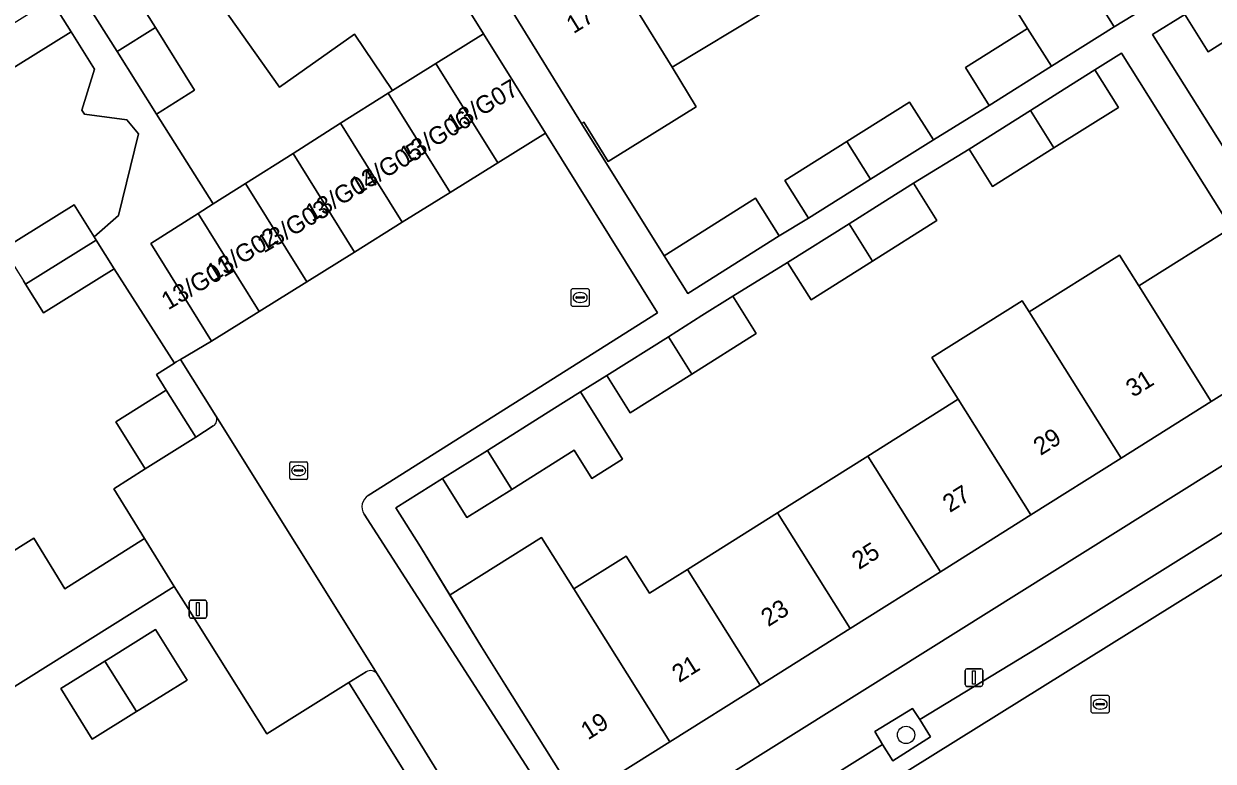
# Model space of a CAD drawing. Extents: x 159664 to 160323, y 385312 to 386115.
# Drawn here: x 160042.7 to 160109.8, y 385865.8 to 385907.3 of the extents above; entities that cross this region are included whole.
import ezdxf

# ---------------------------------------------------------------- set-up
doc = ezdxf.new("R2010")
doc.units = 0
for name, color, linetype in [('IMGEO_Boom', 7, 'Continuous'), ('IMGEO_Erf', 7, 'Continuous'), ('IMGEO_Groenvoorziening', 7, 'Continuous'), ('IMGEO_Hek', 7, 'Continuous'), ('IMGEO_Kolk', 7, 'Continuous'), ('IMGEO_Lichtmast', 7, 'Continuous'), ('IMGEO_Muur', 7, 'Continuous'), ('IMGEO_Pand', 7, 'Continuous'), ('IMGEO_Pand_nummerreeks', 7, 'Continuous'), ('IMGEO_Parkeervlak_open', 7, 'Continuous'), ('IMGEO_Rijbaan_lokaal_open', 7, 'Continuous'), ('IMGEO_Rioolput', 7, 'Continuous'), ('IMGEO_Voetpad_open', 7, 'Continuous')]:
    doc.layers.add(name, color=color, linetype=linetype)

msp = doc.modelspace()

# ---------------------------------------------------------------- linework, layer by layer
at = {"layer": 'IMGEO_Boom'}
msp.add_circle((160092.484, 385867.255), 0.489, dxfattribs=at)
at = {"layer": 'IMGEO_Erf'}
for points in [[(160126.839, 385908.47), (160123.221, 385914.292), (160119.716, 385912.09), (160118.382, 385914.213), (160115.296, 385912.328), (160116.62, 385910.22), (160112.979, 385907.932), (160109.521, 385905.76), (160108.197, 385907.868), (160106.387, 385906.731), (160112.564, 385896.901), (160117.776, 385900.176), (160122.877, 385903.38), (160121.717, 385905.252)], [(160093.943, 385888.53), (160099.032, 385891.727), (160099.43, 385891.094), (160104.519, 385894.291), (160105.604, 385892.565), (160110.817, 385895.84), (160104.64, 385905.681), (160103.136, 385904.736), (160104.46, 385902.628), (160100.815, 385900.338), (160097.361, 385898.168), (160096.037, 385900.276), (160092.906, 385898.349), (160094.23, 385896.241), (160090.592, 385893.956), (160087.131, 385891.781), (160085.807, 385893.889), (160082.713, 385891.979), (160084.037, 385889.871), (160080.399, 385887.585), (160076.938, 385885.411), (160075.614, 385887.519), (160074.124, 385886.584), (160076.502, 385882.799), (160074.763, 385881.707), (160073.764, 385883.296), (160070.256, 385881.092), (160067.724, 385879.501), (160066.344, 385881.698), (160063.721, 385880.05), (160065.101, 385877.853), (160066.757, 385875.136), (160066.776, 385875.148), (160071.939, 385878.386), (160073.757, 385875.486), (160076.705, 385877.338), (160078.024, 385875.238), (160079.31, 385876.045), (160080.158, 385876.578), (160085.247, 385879.775), (160090.337, 385882.973), (160095.426, 385886.17)], [(160017.562, 385899.151), (160016.976, 385898.786), (160016.864, 385898.967), (160013.411, 385904.508), (160011.524, 385903.327), (160035.946, 385864.298), (160048.683, 385843.877), (160069.417, 385856.837), (160067.895, 385859.287), (160061.072, 385870.217), (160056.435, 385867.318), (160052.008, 385874.381), (160051.226, 385875.622), (160036.993, 385866.722), (160033.548, 385872.248), (160030.317, 385877.411), (160029.732, 385877.045), (160029.621, 385877.223), (160026.283, 385882.566), (160026.158, 385882.766), (160027.345, 385883.508), (160024.13, 385888.65), (160020.789, 385893.991)], [(160116.716, 385886.45), (160114.912, 385889.321), (160109.699, 385886.046), (160104.61, 385882.849), (160099.521, 385879.652), (160094.432, 385876.454), (160089.342, 385873.256), (160084.253, 385870.059), (160079.165, 385866.862), (160074.076, 385863.665), (160075.884, 385860.864)], [(160050.171, 385873.193), (160051.948, 385870.346), (160049.274, 385868.684), (160049.094, 385868.572), (160046.6, 385867.021), (160044.828, 385869.865), (160047.316, 385871.414), (160047.5, 385871.529)]]:
    msp.add_lwpolyline(points, close=True, dxfattribs=at)
for points in [[(160101.284, 385911.84), (160104.221, 385907.166), (160107.37, 385909.108)], [(160047.941, 385910.651), (160050.158, 385907.127), (160052.374, 385903.603), (160050.216, 385902.245), (160053.421, 385897.182), (160055.247, 385898.338), (160057.926, 385900.034), (160060.605, 385901.73), (160063.284, 385903.426), (160063.535, 385903.585), (160061.393, 385906.756), (160057.162, 385903.768), (160053.366, 385909.143)], [(160084.541, 385908.057), (160079.289, 385904.884), (160080.657, 385902.663), (160075.692, 385899.577), (160074.315, 385901.792), (160074.183, 385901.71), (160078.841, 385894.266), (160083.99, 385897.501), (160085.324, 385895.378), (160086.982, 385896.372), (160085.644, 385898.503), (160089.148, 385900.705), (160092.688, 385902.929), (160094.027, 385900.798), (160097.176, 385902.74), (160095.838, 385904.871), (160099.342, 385907.073), (160097.759, 385909.621)], [(160041.596, 385894.65), (160045.576, 385897.131), (160046.701, 385895.328), (160048.08, 385896.529), (160049.216, 385901.132), (160048.554, 385901.921), (160046.156, 385902.244), (160046.014, 385902.47), (160046.729, 385904.777), (160045.416, 385906.887), (160041.433, 385904.408)], [(160041.591, 385877.278), (160043.3, 385878.347), (160045.063, 385875.496), (160049.546, 385878.331), (160047.808, 385881.122), (160049.592, 385882.259), (160047.93, 385884.908), (160050.768, 385886.689), (160050.227, 385887.569), (160051.229, 385888.21), (160047.826, 385893.524), (160043.846, 385891.042), (160042.835, 385892.664), (160042.721, 385892.846)]]:
    msp.add_lwpolyline(points, dxfattribs=at)
at = {"layer": 'IMGEO_Groenvoorziening'}
msp.add_lwpolyline([(160093.873, 385867.136), (160093.257, 385868.13), (160092.858, 385868.751), (160090.725, 385867.449), (160091.151, 385866.716), (160091.737, 385865.792)], close=True, dxfattribs=at)
at = {"layer": 'IMGEO_Hek'}
for points in [[(160051.574, 385888.418), (160053.317, 385889.442)], [(160051.328, 385888.274), (160051.574, 385888.418)], [(160052.008, 385874.381), (160051.226, 385875.622)]]:
    msp.add_lwpolyline(points, dxfattribs=at)
at = {"layer": 'IMGEO_Kolk'}
for p, q in [((160073.686, 385892.41), (160074.538, 385892.41)), ((160073.611, 385891.484), (160073.611, 385892.336)), ((160073.87, 385891.904), (160073.87, 385891.916)), ((160074.308, 385891.867), (160073.91, 385891.867)), ((160073.913, 385891.953), (160074.311, 385891.953)), ((160074.099, 385892.19), (160074.124, 385892.19)), ((160074.354, 385891.916), (160074.354, 385891.904)), ((160074.612, 385892.336), (160074.612, 385891.484)), ((160074.538, 385891.41), (160073.686, 385891.41)), ((160074.122, 385891.63), (160074.097, 385891.63)), ((160057.735, 385881.728), (160057.735, 385882.58)), ((160057.81, 385882.654), (160058.662, 385882.654)), ((160058.223, 385882.434), (160058.248, 385882.434)), ((160058.736, 385882.58), (160058.736, 385881.728)), ((160058.662, 385881.654), (160057.81, 385881.654)), ((160057.994, 385882.148), (160057.994, 385882.16)), ((160058.432, 385882.111), (160058.034, 385882.111)), ((160058.037, 385882.197), (160058.435, 385882.197)), ((160058.246, 385881.874), (160058.221, 385881.874)), ((160058.478, 385882.16), (160058.478, 385882.148))]:
    msp.add_line(p, q, dxfattribs=at)
for points in [[(160073.686, 385892.41), (160074.538, 385892.41)], [(160073.611, 385891.484), (160073.611, 385892.336)], [(160074.612, 385892.336), (160074.612, 385891.484)], [(160074.538, 385891.41), (160073.686, 385891.41)], [(160057.735, 385881.728), (160057.735, 385882.58)], [(160057.81, 385882.654), (160058.662, 385882.654)], [(160058.736, 385882.58), (160058.736, 385881.728)], [(160058.662, 385881.654), (160057.81, 385881.654)]]:
    msp.add_lwpolyline(points, dxfattribs=at)
for centre, radius, start, end in [((160073.688, 385892.334), 0.0765, 91.55205, 178.44795), ((160073.688, 385892.334), 0.0765, 91.55205, 178.44795), ((160074.536, 385892.334), 0.0765, 1.55205, 88.44795), ((160074.536, 385892.334), 0.0765, 1.55205, 88.44795), ((160073.91, 385891.913), 0.0403, 85.87752, 175.75265), ((160073.907, 385891.903), 0.0366, 178.93798, 274.71019), ((160074.311, 385891.91), 0.043, 264.86636, 352.45326), ((160074.315, 385891.915), 0.0386, 1.73085, 96.63898), ((160073.688, 385891.486), 0.0765, 181.55205, 268.44795), ((160073.688, 385891.486), 0.0765, 181.55205, 268.44795), ((160074.536, 385891.486), 0.0765, 271.55205, 358.44795), ((160074.536, 385891.486), 0.0765, 271.55205, 358.44795), ((160057.812, 385882.578), 0.0765, 91.55205, 178.44795), ((160057.812, 385882.578), 0.0765, 91.55205, 178.44795), ((160058.66, 385882.578), 0.0765, 1.55205, 88.44795), ((160058.66, 385882.578), 0.0765, 1.55205, 88.44795), ((160057.812, 385881.73), 0.0765, 181.55205, 268.44795), ((160057.812, 385881.73), 0.0765, 181.55205, 268.44795), ((160058.034, 385882.157), 0.0403, 85.87752, 175.75265), ((160058.031, 385882.147), 0.0366, 178.93798, 274.71019), ((160058.435, 385882.154), 0.043, 264.86636, 352.45326), ((160058.439, 385882.159), 0.0386, 1.73085, 96.63898), ((160058.66, 385881.73), 0.0765, 271.55205, 358.44795), ((160058.66, 385881.73), 0.0765, 271.55205, 358.44795)]:
    msp.add_arc(centre, radius, start, end, dxfattribs=at)
for centre, major_axis, ratio, start_param, end_param in [((160074.098, 385891.91), (-0.387, 0.002), 0.722429, 4.712389, 7.853982), ((160074.123, 385891.91), (-0.39, 0.002), 0.717154, 1.570796, 4.712389), ((160058.222, 385882.154), (-0.387, 0.002), 0.722429, 4.712389, 7.853982), ((160058.247, 385882.154), (-0.39, 0.002), 0.717154, 1.570796, 4.712389)]:
    msp.add_ellipse(centre, major_axis=major_axis, ratio=ratio, start_param=start_param, end_param=end_param, dxfattribs=at)
at = {"layer": 'IMGEO_Lichtmast'}
for p, q in [((160052.067, 385873.943), (160052.067, 385874.743)), ((160052.067, 385874.743), (160052.067, 385873.943)), ((160052.167, 385874.843), (160052.957, 385874.843)), ((160052.957, 385874.843), (160052.167, 385874.843)), ((160053.057, 385874.743), (160053.057, 385873.943)), ((160053.057, 385873.943), (160053.057, 385874.743)), ((160052.957, 385873.843), (160052.167, 385873.843)), ((160052.167, 385873.843), (160052.957, 385873.843)), ((160095.919, 385870.986), (160096.709, 385870.986)), ((160096.709, 385870.986), (160095.919, 385870.986)), ((160095.819, 385870.086), (160095.819, 385870.886)), ((160095.819, 385870.886), (160095.819, 385870.086)), ((160096.809, 385870.886), (160096.809, 385870.086)), ((160096.809, 385870.086), (160096.809, 385870.886)), ((160096.709, 385869.986), (160095.919, 385869.986)), ((160095.919, 385869.986), (160096.709, 385869.986))]:
    msp.add_line(p, q, dxfattribs=at)
for points in [[(160052.487, 385874.718), (160052.637, 385874.718), (160052.637, 385873.968), (160052.487, 385873.968), (160052.487, 385874.718)], [(160096.239, 385870.861), (160096.389, 385870.861), (160096.389, 385870.111), (160096.239, 385870.111), (160096.239, 385870.861)]]:
    msp.add_lwpolyline(points, dxfattribs=at)
for centre, start, end in [((160052.167, 385874.743), 90, 180), ((160052.167, 385874.743), 90, 180), ((160052.957, 385874.743), 0, 90), ((160052.957, 385874.743), 360, 90), ((160052.167, 385873.943), 180, 270), ((160052.167, 385873.943), 180, 270), ((160052.957, 385873.943), 270, 0), ((160052.957, 385873.943), 270, 0), ((160095.919, 385870.886), 90, 180), ((160095.919, 385870.886), 90, 180), ((160096.709, 385870.886), 0, 90), ((160096.709, 385870.886), 360, 90), ((160095.919, 385870.086), 180, 270), ((160095.919, 385870.086), 180, 270), ((160096.709, 385870.086), 270, 0), ((160096.709, 385870.086), 270, 0)]:
    msp.add_arc(centre, 0.1, start, end, dxfattribs=at)
at = {"layer": 'IMGEO_Muur'}
for points in [[(160074.183, 385901.71), (160078.841, 385894.266)], [(160050.768, 385886.689), (160050.227, 385887.569), (160051.328, 385888.274)], [(160049.546, 385878.331), (160047.808, 385881.122), (160049.592, 385882.259)], [(160065.101, 385877.853), (160068.541, 385872.21)], [(160052.008, 385874.381), (160056.435, 385867.318), (160061.072, 385870.217)], [(160061.072, 385870.217), (160067.895, 385859.287)]]:
    msp.add_lwpolyline(points, dxfattribs=at)
at = {"layer": 'IMGEO_Pand'}
for points in [[(160066.34, 385910.485), (160067.916, 385911.581), (160064.485, 385916.622), (160056.342, 385911.145), (160053.366, 385909.143), (160057.162, 385903.768), (160061.393, 385906.756), (160063.535, 385903.585), (160065.974, 385905.104), (160068.657, 385906.776)], [(160080.357, 385914.713), (160080.13, 385915.074), (160074.992, 385911.86), (160075.203, 385911.518), (160079.289, 385904.884), (160084.541, 385908.057)], [(160075.203, 385911.518), (160074.992, 385911.86), (160069.893, 385908.671), (160070.091, 385908.35), (160074.183, 385901.71), (160074.315, 385901.792), (160075.692, 385899.577), (160080.657, 385902.663), (160079.289, 385904.884)], [(160104.221, 385907.166), (160101.284, 385911.84), (160097.759, 385909.621), (160099.342, 385907.073), (160100.678, 385904.94)], [(160050.158, 385907.127), (160047.941, 385910.651), (160045.783, 385909.294), (160047.999, 385905.77)], [(160108.197, 385907.868), (160109.521, 385905.76), (160112.979, 385907.932), (160111.669, 385910.05)], [(160040.307, 385906.205), (160041.433, 385904.408), (160045.416, 385906.887), (160044.292, 385908.693)], [(160047.999, 385905.77), (160050.216, 385902.245), (160052.374, 385903.603), (160050.158, 385907.127)], [(160072.156, 385901.175), (160068.657, 385906.776), (160065.974, 385905.104), (160069.465, 385899.499)], [(160095.838, 385904.871), (160097.176, 385902.74), (160100.678, 385904.94), (160099.342, 385907.073)], [(160065.974, 385905.104), (160063.535, 385903.585), (160063.284, 385903.426), (160066.773, 385897.823), (160069.465, 385899.499)], [(160104.46, 385902.628), (160103.136, 385904.736), (160101.399, 385903.645), (160099.509, 385902.458), (160100.815, 385900.338)], [(160064.082, 385896.147), (160066.773, 385897.823), (160063.284, 385903.426), (160060.605, 385901.73)], [(160094.027, 385900.798), (160092.688, 385902.929), (160089.148, 385900.705), (160090.484, 385898.572)], [(160096.037, 385900.276), (160097.361, 385898.168), (160100.815, 385900.338), (160099.509, 385902.458)], [(160060.605, 385901.73), (160057.926, 385900.034), (160061.391, 385894.47), (160064.082, 385896.147)], [(160085.644, 385898.503), (160086.982, 385896.372), (160090.484, 385898.572), (160089.148, 385900.705)], [(160057.926, 385900.034), (160055.247, 385898.338), (160058.7, 385892.794), (160061.391, 385894.47)], [(160055.247, 385898.338), (160053.421, 385897.182), (160052.568, 385896.642), (160056.008, 385891.118), (160058.7, 385892.794)], [(160094.23, 385896.241), (160092.906, 385898.349), (160091.169, 385897.258), (160089.279, 385896.071), (160090.592, 385893.956)], [(160042.835, 385892.664), (160046.815, 385895.144), (160046.701, 385895.328), (160045.576, 385897.131), (160041.596, 385894.65), (160042.721, 385892.846)], [(160085.324, 385895.378), (160083.99, 385897.501), (160078.841, 385894.266), (160080.175, 385892.143)], [(160049.895, 385894.95), (160053.317, 385889.442), (160056.008, 385891.118), (160052.568, 385896.642)], [(160085.807, 385893.889), (160087.131, 385891.781), (160090.592, 385893.956), (160089.279, 385896.071)], [(160109.699, 385886.046), (160114.912, 385889.321), (160112.252, 385893.554), (160110.817, 385895.84), (160105.604, 385892.565)], [(160043.846, 385891.042), (160047.826, 385893.524), (160046.815, 385895.144), (160042.835, 385892.664)], [(160105.604, 385892.565), (160104.519, 385894.291), (160099.43, 385891.094), (160100.515, 385889.367), (160104.61, 385882.849), (160109.699, 385886.046)], [(160084.037, 385889.871), (160082.713, 385891.979), (160080.976, 385890.888), (160079.086, 385889.701), (160080.399, 385887.585)], [(160100.515, 385889.367), (160099.43, 385891.094), (160099.032, 385891.727), (160093.943, 385888.53), (160095.426, 385886.17), (160099.521, 385879.652), (160104.61, 385882.849)], [(160076.938, 385885.411), (160080.399, 385887.585), (160079.086, 385889.701), (160075.614, 385887.519)], [(160050.768, 385886.689), (160047.93, 385884.908), (160049.592, 385882.259), (160052.431, 385884.04)], [(160074.124, 385886.584), (160072.518, 385885.577), (160068.882, 385883.292), (160070.256, 385881.092), (160073.764, 385883.296), (160074.763, 385881.707), (160076.502, 385882.799)], [(160094.432, 385876.454), (160099.521, 385879.652), (160095.426, 385886.17), (160090.337, 385882.973)], [(160068.882, 385883.292), (160066.344, 385881.698), (160067.724, 385879.501), (160070.256, 385881.092)], [(160089.342, 385873.256), (160094.432, 385876.454), (160090.337, 385882.973), (160085.247, 385879.775)], [(160085.247, 385879.775), (160080.158, 385876.578), (160084.253, 385870.059), (160089.342, 385873.256)], [(160051.226, 385875.622), (160049.546, 385878.331), (160045.063, 385875.496), (160043.3, 385878.347), (160041.591, 385877.278), (160033.548, 385872.248), (160036.993, 385866.722)], [(160073.757, 385875.486), (160071.939, 385878.386), (160066.776, 385875.148), (160066.757, 385875.136), (160068.541, 385872.21), (160069.86, 385870.109), (160073.955, 385863.589), (160074.076, 385863.665), (160079.165, 385866.862)], [(160080.158, 385876.578), (160079.31, 385876.045), (160078.024, 385875.238), (160076.705, 385877.338), (160073.757, 385875.486), (160079.165, 385866.862), (160084.253, 385870.059)], [(160047.316, 385871.414), (160049.094, 385868.572), (160049.274, 385868.684), (160051.948, 385870.346), (160050.171, 385873.193), (160047.5, 385871.529)], [(160044.828, 385869.865), (160046.6, 385867.021), (160049.094, 385868.572), (160047.316, 385871.414)]]:
    msp.add_lwpolyline(points, close=True, dxfattribs=at)
at = {"layer": 'IMGEO_Parkeervlak_open'}
for points in [[(160063.145, 385846.843), (160091.556, 385864.586), (160112.548, 385877.672), (160134.283, 385891.268)], [(160122.453, 385884.847), (160121.825, 385885.847), (160101.83, 385873.354), (160099.827, 385872.1), (160093.257, 385868.13), (160093.873, 385867.136), (160091.737, 385865.792), (160091.151, 385866.716), (160082.406, 385861.229), (160083.032, 385860.228)], [(160062.663, 385870.691), (160053.567, 385885.245)], [(160053.422, 385884.668), (160052.431, 385884.04), (160049.592, 385882.259), (160047.808, 385881.122), (160049.546, 385878.331), (160051.226, 385875.622), (160052.008, 385874.381), (160056.435, 385867.318), (160061.072, 385870.217), (160062.04, 385870.818)]]:
    msp.add_lwpolyline(points, dxfattribs=at)
for centre, radius, start, end in [((160053.188, 385885.034), 0.434, 302.62155, 29.16582), ((160062.275, 385870.379), 0.498, 38.79059, 118.16539)]:
    msp.add_arc(centre, radius, start, end, dxfattribs=at)
at = {"layer": 'IMGEO_Rijbaan_lokaal_open'}
for points in [[(160062.163, 385880.749), (160078.47, 385891.036), (160072.156, 385901.175), (160069.465, 385899.499), (160066.773, 385897.823), (160064.082, 385896.147), (160061.391, 385894.47), (160058.7, 385892.794), (160056.008, 385891.118), (160053.317, 385889.442), (160051.574, 385888.418), (160053.567, 385885.245), (160062.663, 385870.691), (160070.726, 385857.635), (160074.573, 385860.069), (160061.925, 385879.702)], [(160112.548, 385877.672), (160091.556, 385864.586)]]:
    msp.add_lwpolyline(points, dxfattribs=at)
msp.add_arc((160062.567, 385880.107), 0.759, 122.15666, 212.23007, dxfattribs=at)
at = {"layer": 'IMGEO_Rioolput'}
for p, q in [((160102.931, 385868.56), (160102.931, 385869.412)), ((160103.006, 385869.486), (160103.858, 385869.486)), ((160103.19, 385868.98), (160103.19, 385868.992)), ((160103.628, 385868.943), (160103.23, 385868.943)), ((160103.233, 385869.029), (160103.631, 385869.029)), ((160103.419, 385869.266), (160103.444, 385869.266)), ((160103.674, 385868.992), (160103.674, 385868.98)), ((160103.932, 385869.412), (160103.932, 385868.56)), ((160103.858, 385868.486), (160103.006, 385868.486)), ((160103.442, 385868.706), (160103.417, 385868.706))]:
    msp.add_line(p, q, dxfattribs=at)
for points in [[(160102.931, 385868.56), (160102.931, 385869.412)], [(160103.006, 385869.486), (160103.858, 385869.486)], [(160103.932, 385869.412), (160103.932, 385868.56)], [(160103.858, 385868.486), (160103.006, 385868.486)]]:
    msp.add_lwpolyline(points, dxfattribs=at)
for centre, radius, start, end in [((160103.008, 385869.41), 0.0765, 91.55205, 178.44795), ((160103.008, 385869.41), 0.0765, 91.55205, 178.44795), ((160103.23, 385868.989), 0.0403, 85.87752, 175.75265), ((160103.227, 385868.979), 0.0366, 178.93798, 274.71019), ((160103.631, 385868.986), 0.043, 264.86636, 352.45326), ((160103.635, 385868.991), 0.0386, 1.73085, 96.63898), ((160103.856, 385869.41), 0.0765, 1.55205, 88.44795), ((160103.856, 385869.41), 0.0765, 1.55205, 88.44795), ((160103.008, 385868.562), 0.0765, 181.55205, 268.44795), ((160103.008, 385868.562), 0.0765, 181.55205, 268.44795), ((160103.856, 385868.562), 0.0765, 271.55205, 358.44795), ((160103.856, 385868.562), 0.0765, 271.55205, 358.44795)]:
    msp.add_arc(centre, radius, start, end, dxfattribs=at)
for centre, major_axis, ratio, start_param, end_param in [((160103.418, 385868.986), (-0.387, 0.002), 0.722429, 4.712389, 7.853982), ((160103.443, 385868.986), (-0.39, 0.002), 0.717154, 1.570796, 4.712389)]:
    msp.add_ellipse(centre, major_axis=major_axis, ratio=ratio, start_param=start_param, end_param=end_param, dxfattribs=at)
at = {"layer": 'IMGEO_Voetpad_open'}
for points in [[(160066.34, 385910.485), (160068.657, 385906.776), (160072.156, 385901.175), (160078.47, 385891.036), (160062.163, 385880.749)], [(160044.292, 385908.693), (160045.416, 385906.887), (160046.729, 385904.777), (160046.014, 385902.47), (160046.156, 385902.244), (160048.554, 385901.921), (160049.216, 385901.132), (160048.08, 385896.529), (160046.701, 385895.328), (160046.815, 385895.144), (160047.826, 385893.524), (160051.229, 385888.21), (160051.328, 385888.274), (160051.574, 385888.418), (160053.317, 385889.442), (160049.895, 385894.95), (160052.568, 385896.642), (160053.421, 385897.182), (160050.216, 385902.245), (160047.999, 385905.77), (160045.783, 385909.294)], [(160107.37, 385909.108), (160104.221, 385907.166), (160100.678, 385904.94), (160097.176, 385902.74), (160094.027, 385900.798), (160090.484, 385898.572), (160086.982, 385896.372), (160085.324, 385895.378), (160080.175, 385892.143), (160078.841, 385894.266), (160074.183, 385901.71), (160070.091, 385908.35)], [(160106.387, 385906.731), (160108.197, 385907.868)], [(160112.564, 385896.901), (160106.387, 385906.731)], [(160073.955, 385863.589), (160069.86, 385870.109), (160068.541, 385872.21), (160066.757, 385875.136), (160065.101, 385877.853), (160063.721, 385880.05), (160066.344, 385881.698), (160068.882, 385883.292), (160072.518, 385885.577), (160074.124, 385886.584), (160075.614, 385887.519), (160079.086, 385889.701), (160080.976, 385890.888), (160082.713, 385891.979), (160085.807, 385893.889), (160089.279, 385896.071), (160091.169, 385897.258), (160092.906, 385898.349), (160096.037, 385900.276), (160099.509, 385902.458), (160101.399, 385903.645), (160103.136, 385904.736), (160104.64, 385905.681), (160110.817, 385895.84)], [(160141.001, 385901.665), (160139.28, 385900.589), (160118.445, 385887.533), (160116.716, 385886.45), (160075.884, 385860.864), (160074.573, 385860.069), (160070.726, 385857.635), (160069.417, 385856.837), (160048.683, 385843.877), (160050.819, 385840.388)], [(160051.574, 385888.418), (160051.328, 385888.274), (160051.229, 385888.21), (160050.227, 385887.569), (160050.768, 385886.689), (160052.431, 385884.04), (160053.422, 385884.668)], [(160053.567, 385885.245), (160051.574, 385888.418)], [(160064.771, 385850.208), (160072.444, 385854.983), (160072.221, 385855.373), (160076.054, 385857.762), (160076.28, 385857.388), (160079.096, 385859.135), (160078.564, 385859.903), (160081.927, 385861.962), (160082.406, 385861.229), (160091.151, 385866.716), (160090.725, 385867.449), (160092.858, 385868.751), (160093.257, 385868.13), (160099.827, 385872.1), (160101.83, 385873.354), (160121.825, 385885.847)], [(160061.925, 385879.702), (160074.573, 385860.069)], [(160062.04, 385870.818), (160061.072, 385870.217), (160067.895, 385859.287), (160069.417, 385856.837), (160070.726, 385857.635), (160062.663, 385870.691)]]:
    msp.add_lwpolyline(points, dxfattribs=at)
for centre, radius, start, end in [((160053.188, 385885.034), 0.434, 302.62155, 29.16582), ((160062.567, 385880.107), 0.759, 122.15666, 212.23007), ((160062.275, 385870.379), 0.498, 38.79059, 118.16539)]:
    msp.add_arc(centre, radius, start, end, dxfattribs=at)

# ---------------------------------------------------------------- texts
at = {"layer": 'IMGEO_Pand_nummerreeks'}
for s, rotation, p in [('17', 31.79343, (160073.734, 385906.75)), ('13/G07', 30.72049, (160066.957, 385901.167)), ('13/G06', 31.24358, (160064.318, 385899.402)), ('13/G05', 30.67168, (160061.53, 385897.668)), ('13/G04', 30.0676, (160058.981, 385896.147)), ('13/G03', 30.59236, (160056.28, 385894.392)), ('13/G02', 31.48976, (160053.437, 385892.785)), ('13/G01', 30.38108, (160050.877, 385891.181)), ('31', 32.1372, (160105.288, 385886.251)), ('29', 32.1372, (160100.072, 385882.973)), ('27', 32.13986, (160094.953, 385879.757)), ('25', 32.13986, (160089.833, 385876.54)), ('23', 32.13986, (160084.713, 385873.324)), ('21', 32.13986, (160079.69, 385870.168)), ('19', 32.1372, (160074.551, 385866.94))]:
    msp.add_text(s, height=1, rotation=rotation, dxfattribs=at).set_placement(p)

doc.saveas('drawing.dxf')
